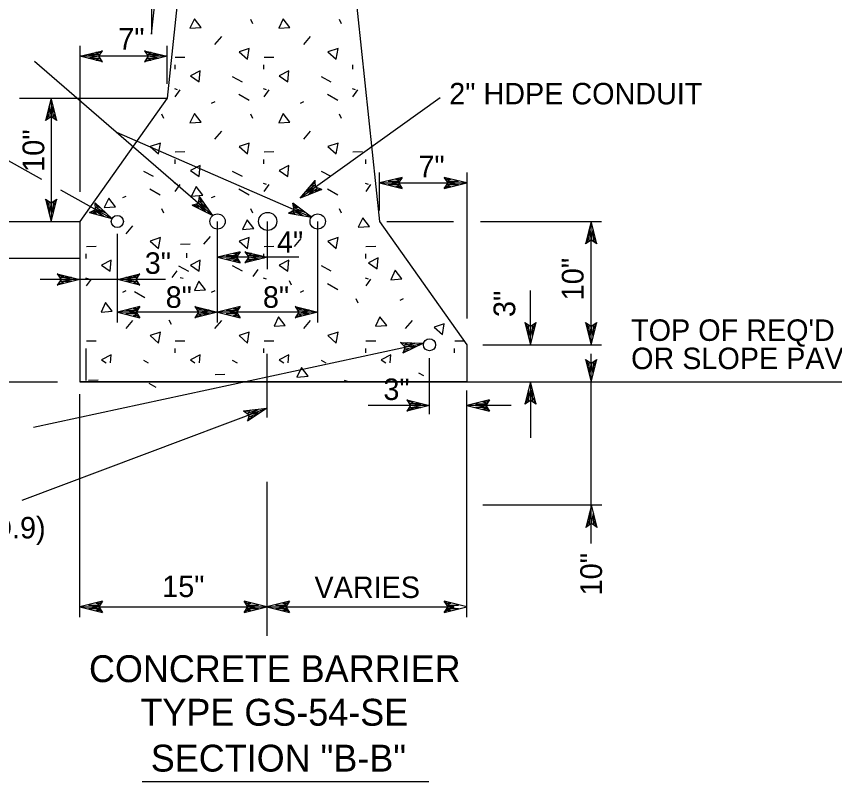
# Model space of a CAD drawing. Extents: x 504255 to 505955, y 659986 to 661086.
# Drawn here: x 504800.9 to 505019.2, y 660598.4 to 660802.7 of the extents above; entities that cross this region are included whole.
import ezdxf

# ---------------------------------------------------------------- set-up
doc = ezdxf.new("R2010")
doc.units = 0
for name, color, linetype in [('Level1', 7, 'Continuous'), ('Level3', 7, 'Continuous'), ('Level63', 7, 'Continuous')]:
    doc.layers.add(name, color=color, linetype=linetype)

msp = doc.modelspace()

# ---------------------------------------------------------------- linework, layer by layer
at = {"layer": 'Level1'}
for p, q in [((504836.94, 660797.95), (504841, 660836.25)), ((504836.94, 660836.25), (504836.94, 660797.95)), ((504817.81, 660794.84), (504817.81, 660755.89)), ((504841.09, 660784.74), (504841.09, 660794.84)), ((504841.09, 660792.07), (504817.81, 660792.07)), ((504805.69, 660790.75), (504853.25, 660749.56)), ((504801.72, 660780.9), (504841.09, 660780.9)), ((504810.12, 660780.9), (504810.12, 660747.99)), ((504913.88, 660780.98), (504876.56, 660754.22)), ((504827.59, 660771.79), (504879.56, 660749.11)), ((504792.67, 660767.62), (504807.54, 660759.29)), ((504897.78, 660750.93), (504897.78, 660761.02)), ((504921.05, 660761.02), (504921.05, 660722.07)), ((504812.63, 660756.44), (504826.35, 660748.74)), ((504897.78, 660758.26), (504921.05, 660758.26)), ((504795.68, 660747.99), (504817.81, 660747.99)), ((504854.52, 660721.03), (504854.52, 660747.99)), ((504867.88, 660735.21), (504867.88, 660747.99)), ((504881.25, 660721.03), (504881.25, 660747.99)), ((504899.7, 660747.99), (504917.49, 660747.99)), ((504924.66, 660747.99), (504957, 660747.99)), ((504954.2, 660715.08), (504954.2, 660747.99)), ((504827.79, 660721.03), (504827.79, 660744.66)), ((504876.24, 660738.42), (504854.52, 660738.42)), ((504840.61, 660732.51), (504807.19, 660732.51)), ((504938.01, 660715.08), (504938.01, 660729.53)), ((504854.52, 660723.79), (504827.79, 660723.79)), ((504881.25, 660723.79), (504854.52, 660723.79)), ((504805.43, 660693.05), (504909.51, 660715.51)), ((504925.29, 660715.08), (504957, 660715.08)), ((504867.68, 660712.65), (504867.68, 660695.64)), ((504911.08, 660696.5), (504911.08, 660711.53)), ((504954.2, 660662), (504954.2, 660712.65)), ((504768.57, 660705.2), (504811.82, 660705.2)), ((504938.01, 660705.2), (504938.01, 660690.18)), ((504817.81, 660642.32), (504817.81, 660701.86)), ((504921.05, 660642.32), (504921.05, 660702.87)), ((504802.41, 660673.61), (504867.67, 660698.15)), ((504911.08, 660698.82), (504894.72, 660698.82)), ((504932.88, 660698.82), (504921.05, 660698.82)), ((504867.69, 660678.46), (504867.69, 660637.37)), ((504925.29, 660672.29), (504957.1, 660672.29)), ((504817.81, 660645.08), (504867.69, 660645.08)), ((504867.69, 660645.08), (504917.56, 660645.08)), ((504834.41, 660598.43), (504910.91, 660598.43))]:
    msp.add_line(p, q, dxfattribs=at)
for points in [[(504847.43, 660840.63), (504841.09, 660780.9)], [(504887.94, 660840.63), (504897.78, 660747.99)], [(504823.85, 660790.58), (504817.81, 660792.07), (504823.85, 660793.57), (504823.14, 660793.07), (504822.09, 660793.07), (504823.1, 660792.57), (504820.08, 660792.57), (504822.77, 660792.07), (504820.08, 660791.57), (504823.1, 660791.57), (504822.09, 660791.08), (504823.14, 660791.08), (504823.85, 660790.58), (504822.85, 660792.07), (504823.85, 660793.57)], [(504835.04, 660793.57), (504841.09, 660792.07), (504835.04, 660790.58), (504835.76, 660791.08), (504836.8, 660791.08), (504835.79, 660791.57), (504838.81, 660791.57), (504836.13, 660792.07), (504838.81, 660792.57), (504835.79, 660792.57), (504836.8, 660793.07), (504835.76, 660793.07), (504835.04, 660793.57), (504836.05, 660792.07), (504835.04, 660790.58)], [(504811.63, 660774.92), (504810.12, 660780.9), (504808.61, 660774.92), (504809.12, 660775.63), (504809.12, 660776.67), (504809.62, 660775.67), (504809.62, 660778.66), (504810.12, 660776), (504810.62, 660778.66), (504810.62, 660775.67), (504811.13, 660776.67), (504811.13, 660775.63), (504811.63, 660774.92), (504810.12, 660775.92), (504808.61, 660774.92)], [(504841.09, 660780.9), (504817.81, 660747.99)], [(504882.32, 660756.51), (504876.56, 660754.22), (504880.56, 660758.93), (504880.27, 660758.11), (504879.43, 660757.51), (504880.55, 660757.69), (504878.1, 660755.93), (504880.57, 660757.1), (504878.68, 660755.13), (504881.14, 660756.89), (504880.61, 660755.89), (504881.45, 660756.51), (504882.32, 660756.51), (504880.63, 660757.14), (504880.56, 660758.93)], [(504903.82, 660759.75), (504897.78, 660758.26), (504903.82, 660756.77), (504903.11, 660757.26), (504902.06, 660757.26), (504903.07, 660757.76), (504900.05, 660757.76), (504902.74, 660758.26), (504900.05, 660758.75), (504903.07, 660758.75), (504902.06, 660759.26), (504903.11, 660759.26), (504903.82, 660759.75), (504902.81, 660758.26), (504903.82, 660756.77)], [(504915.02, 660756.77), (504921.05, 660758.26), (504915.02, 660759.75), (504915.73, 660759.26), (504916.77, 660759.26), (504915.76, 660758.75), (504918.78, 660758.75), (504916.1, 660758.26), (504918.78, 660757.76), (504915.76, 660757.76), (504916.77, 660757.26), (504915.73, 660757.26), (504915.02, 660756.77), (504916.02, 660758.26), (504915.02, 660759.75)], [(504847.72, 660752.37), (504853.25, 660749.56), (504849.7, 660754.62), (504849.91, 660753.78), (504850.69, 660753.1), (504849.6, 660753.38), (504851.88, 660751.41), (504849.52, 660752.79), (504851.22, 660750.66), (504848.94, 660752.64), (504849.37, 660751.6), (504848.59, 660752.28), (504847.72, 660752.37), (504849.47, 660752.84), (504849.7, 660754.62)], [(504808.61, 660753.97), (504810.12, 660747.99), (504811.63, 660753.97), (504811.13, 660753.26), (504811.13, 660752.23), (504810.63, 660753.23), (504810.63, 660750.24), (504810.12, 660752.9), (504809.62, 660750.24), (504809.62, 660753.23), (504809.12, 660752.23), (504809.12, 660753.26), (504808.61, 660753.97), (504810.12, 660752.97), (504811.63, 660753.97)], [(504820.36, 660750.39), (504826.35, 660748.74), (504821.84, 660752.99), (504822.22, 660752.21), (504823.12, 660751.7), (504822, 660751.76), (504824.62, 660750.28), (504822.04, 660751.16), (504824.14, 660749.42), (504821.5, 660750.89), (504822.13, 660749.96), (504821.23, 660750.48), (504820.36, 660750.39), (504821.98, 660751.2), (504821.84, 660752.99)], [(504873.44, 660750.16), (504879.56, 660749.11), (504874.65, 660752.89), (504875.1, 660752.15), (504876.05, 660751.73), (504874.92, 660751.68), (504877.69, 660750.47), (504875.03, 660751.09), (504877.29, 660749.56), (504874.52, 660750.77), (504875.24, 660749.91), (504874.29, 660750.33), (504873.44, 660750.16), (504874.96, 660751.13), (504874.65, 660752.89)], [(504817.81, 660747.99), (504817.81, 660705.2)], [(504897.78, 660747.99), (504921.05, 660715.08)], [(504955.71, 660742.01), (504954.2, 660747.99), (504952.7, 660742.01), (504953.2, 660742.72), (504953.2, 660743.75), (504953.7, 660742.75), (504953.7, 660745.75), (504954.2, 660743.08), (504954.71, 660745.75), (504954.71, 660742.75), (504955.21, 660743.75), (504955.21, 660742.72), (504955.71, 660742.01), (504954.2, 660743.01), (504952.7, 660742.01)], [(504860.56, 660739.92), (504854.52, 660738.42), (504860.56, 660736.93), (504859.85, 660737.43), (504858.8, 660737.43), (504859.81, 660737.93), (504856.79, 660737.93), (504859.47, 660738.42), (504856.79, 660738.92), (504859.81, 660738.92), (504858.8, 660739.42), (504859.85, 660739.42), (504860.56, 660739.92), (504859.55, 660738.42), (504860.56, 660736.93)], [(504861.84, 660739.92), (504867.88, 660738.42), (504861.84, 660736.93), (504862.56, 660737.43), (504863.6, 660737.43), (504862.59, 660737.93), (504865.61, 660737.93), (504862.93, 660738.42), (504865.61, 660738.92), (504862.59, 660738.92), (504863.6, 660739.42), (504862.56, 660739.42), (504861.84, 660739.92), (504862.85, 660738.42), (504861.84, 660736.93)], [(504811.77, 660734), (504817.81, 660732.51), (504811.77, 660731.02), (504812.49, 660731.51), (504813.53, 660731.51), (504812.52, 660732.01), (504815.54, 660732.01), (504812.86, 660732.51), (504815.54, 660733.01), (504812.52, 660733.01), (504813.53, 660733.51), (504812.49, 660733.51), (504811.77, 660734), (504812.78, 660732.51), (504811.77, 660731.02)], [(504833.82, 660731.02), (504827.79, 660732.51), (504833.82, 660734), (504833.11, 660733.51), (504832.07, 660733.51), (504833.08, 660733.01), (504830.06, 660733.01), (504832.74, 660732.51), (504830.06, 660732.01), (504833.08, 660732.01), (504832.07, 660731.51), (504833.11, 660731.51), (504833.82, 660731.02), (504832.82, 660732.51), (504833.82, 660734)], [(504833.83, 660725.29), (504827.79, 660723.79), (504833.83, 660722.3), (504833.11, 660722.8), (504832.07, 660722.8), (504833.08, 660723.3), (504830.06, 660723.3), (504832.74, 660723.79), (504830.06, 660724.29), (504833.08, 660724.29), (504832.07, 660724.79), (504833.11, 660724.79), (504833.83, 660725.29), (504832.82, 660723.79), (504833.83, 660722.3)], [(504848.48, 660725.29), (504854.52, 660723.79), (504848.48, 660722.3), (504849.19, 660722.8), (504850.23, 660722.8), (504849.23, 660723.3), (504852.25, 660723.3), (504849.57, 660723.79), (504852.25, 660724.29), (504849.23, 660724.29), (504850.23, 660724.79), (504849.19, 660724.79), (504848.48, 660725.29), (504849.49, 660723.79), (504848.48, 660722.3)], [(504860.56, 660725.29), (504854.52, 660723.79), (504860.56, 660722.3), (504859.85, 660722.8), (504858.8, 660722.8), (504859.81, 660723.3), (504856.79, 660723.3), (504859.47, 660723.79), (504856.79, 660724.29), (504859.81, 660724.29), (504858.8, 660724.79), (504859.85, 660724.79), (504860.56, 660725.29), (504859.55, 660723.79), (504860.56, 660722.3)], [(504875.21, 660725.29), (504881.25, 660723.79), (504875.21, 660722.3), (504875.92, 660722.8), (504876.97, 660722.8), (504875.96, 660723.3), (504878.98, 660723.3), (504876.3, 660723.79), (504878.98, 660724.29), (504875.96, 660724.29), (504876.97, 660724.79), (504875.92, 660724.79), (504875.21, 660725.29), (504876.22, 660723.79), (504875.21, 660722.3)], [(504936.5, 660721.05), (504938.01, 660715.08), (504939.52, 660721.05), (504939.02, 660720.35), (504939.02, 660719.32), (504938.52, 660720.31), (504938.52, 660717.33), (504938.01, 660719.98), (504937.51, 660717.33), (504937.51, 660720.31), (504937.01, 660719.32), (504937.01, 660720.35), (504936.5, 660721.05), (504938.01, 660720.06), (504939.52, 660721.05)], [(504952.7, 660721.04), (504954.2, 660715.08), (504955.71, 660721.04), (504955.21, 660720.34), (504955.21, 660719.31), (504954.71, 660720.31), (504954.71, 660717.32), (504954.2, 660719.98), (504953.7, 660717.32), (504953.7, 660720.31), (504953.2, 660719.31), (504953.2, 660720.34), (504952.7, 660721.04), (504954.2, 660720.05), (504955.71, 660721.04)], [(504903.3, 660715.7), (504909.51, 660715.51), (504903.94, 660712.78), (504904.53, 660713.42), (504905.54, 660713.64), (504904.45, 660713.91), (504907.4, 660714.56), (504904.67, 660714.47), (504907.19, 660715.52), (504904.24, 660714.88), (504905.12, 660715.59), (504904.1, 660715.36), (504903.3, 660715.7), (504904.6, 660714.45), (504903.94, 660712.78)], [(504921.05, 660715.08), (504921.05, 660705.2)], [(504952.7, 660711.17), (504954.2, 660705.2), (504955.71, 660711.17), (504955.21, 660710.47), (504955.21, 660709.44), (504954.71, 660710.44), (504954.71, 660707.45), (504954.2, 660710.11), (504953.7, 660707.45), (504953.7, 660710.44), (504953.2, 660709.44), (504953.2, 660710.47), (504952.7, 660711.17), (504954.2, 660710.18), (504955.71, 660711.17)], [(504921.05, 660705.2), (504817.81, 660705.2)], [(504939.52, 660699.23), (504938.01, 660705.2), (504936.5, 660699.23), (504937.01, 660699.93), (504937.01, 660700.96), (504937.51, 660699.96), (504937.51, 660702.96), (504938.01, 660700.29), (504938.51, 660702.96), (504938.51, 660699.96), (504939.02, 660700.96), (504939.02, 660699.93), (504939.52, 660699.23), (504938.01, 660700.22), (504936.5, 660699.23)], [(504905.04, 660700.32), (504911.08, 660698.82), (504905.04, 660697.33), (504905.75, 660697.83), (504906.79, 660697.83), (504905.79, 660698.33), (504908.8, 660698.33), (504906.12, 660698.82), (504908.8, 660699.32), (504905.79, 660699.32), (504906.79, 660699.82), (504905.75, 660699.82), (504905.04, 660700.32), (504906.05, 660698.82), (504905.04, 660697.33)], [(504927.09, 660700.32), (504921.05, 660698.82), (504927.09, 660697.33), (504926.38, 660697.83), (504925.34, 660697.83), (504926.34, 660698.33), (504923.32, 660698.33), (504926.01, 660698.82), (504923.32, 660699.32), (504926.34, 660699.32), (504925.34, 660699.82), (504926.38, 660699.82), (504927.09, 660700.32), (504926.08, 660698.82), (504927.09, 660697.33)], [(504861.49, 660697.43), (504867.67, 660698.15), (504862.56, 660694.63), (504863.05, 660695.35), (504864.02, 660695.72), (504862.9, 660695.83), (504865.72, 660696.9), (504863.04, 660696.41), (504865.38, 660697.82), (504862.55, 660696.76), (504863.31, 660697.58), (504862.34, 660697.21), (504861.49, 660697.43), (504862.97, 660696.38), (504862.56, 660694.63)], [(504955.82, 660666.31), (504954.31, 660672.29), (504952.8, 660666.31), (504953.31, 660667.01), (504953.31, 660668.05), (504953.81, 660667.05), (504953.81, 660670.04), (504954.31, 660667.38), (504954.81, 660670.04), (504954.81, 660667.05), (504955.31, 660668.05), (504955.31, 660667.01), (504955.82, 660666.31), (504954.31, 660667.31), (504952.8, 660666.31)], [(504823.86, 660646.58), (504817.81, 660645.08), (504823.86, 660643.59), (504823.14, 660644.09), (504822.1, 660644.09), (504823.1, 660644.58), (504820.09, 660644.58), (504822.77, 660645.08), (504820.09, 660645.58), (504823.1, 660645.58), (504822.1, 660646.08), (504823.14, 660646.08), (504823.86, 660646.58), (504822.85, 660645.08), (504823.86, 660643.59)], [(504861.65, 660643.59), (504867.69, 660645.08), (504861.65, 660646.58), (504862.36, 660646.08), (504863.41, 660646.08), (504862.4, 660645.58), (504865.42, 660645.58), (504862.73, 660645.08), (504865.42, 660644.58), (504862.4, 660644.58), (504863.41, 660644.09), (504862.36, 660644.09), (504861.65, 660643.59), (504862.65, 660645.08), (504861.65, 660646.58)], [(504873.73, 660646.58), (504867.69, 660645.08), (504873.73, 660643.59), (504873.01, 660644.09), (504871.97, 660644.09), (504872.98, 660644.58), (504869.96, 660644.58), (504872.64, 660645.08), (504869.96, 660645.58), (504872.98, 660645.58), (504871.97, 660646.08), (504873.01, 660646.08), (504873.73, 660646.58), (504872.72, 660645.08), (504873.73, 660643.59)], [(504915.02, 660643.59), (504921.05, 660645.08), (504915.02, 660646.58), (504915.73, 660646.08), (504916.77, 660646.08), (504915.76, 660645.58), (504918.78, 660645.58), (504916.1, 660645.08), (504918.78, 660644.58), (504915.76, 660644.58), (504916.77, 660644.09), (504915.73, 660644.09), (504915.02, 660643.59), (504916.02, 660645.08), (504915.02, 660646.58)]]:
    msp.add_lwpolyline(points, dxfattribs=at)
for points in [[(504829.34, 660750.54), (504829.34, 660750.54), (504829.35, 660750.54)], [(505010.52, 660705.2), (505010.52, 660705.2), (505010.52, 660705.2)]]:
    msp.add_lwpolyline(points, close=True, dxfattribs=at)
at = {"layer": 'Level3'}
for p, q in [((504863.29, 660801.98), (504863.84, 660800.83)), ((504886.98, 660801.98), (504887.54, 660800.83)), ((504855.55, 660797.34), (504853.71, 660795.2)), ((504879.25, 660797.34), (504877.42, 660795.2)), ((504845.84, 660791.8), (504843.22, 660791.75)), ((504869.54, 660791.8), (504866.93, 660791.75)), ((504843.09, 660789.81), (504843.09, 660788.63)), ((504866.8, 660789.81), (504866.8, 660788.63)), ((504890.49, 660789.81), (504890.49, 660788.63)), ((504858.43, 660786.69), (504861.08, 660785.28)), ((504882.13, 660786.69), (504884.78, 660785.28)), ((504843.88, 660783.13), (504843.09, 660783.36)), ((504844.47, 660783.13), (504843.15, 660781.27)), ((504867.58, 660783.13), (504866.8, 660783.36)), ((504868.17, 660783.13), (504866.85, 660781.27)), ((504891.29, 660783.13), (504890.49, 660783.36)), ((504891.88, 660783.13), (504890.56, 660781.27)), ((504860.18, 660781.97), (504862.92, 660780.36)), ((504883.88, 660781.97), (504886.62, 660780.36)), ((504852.94, 660779.6), (504853.88, 660780.04)), ((504876.64, 660779.6), (504877.58, 660780.04)), ((504839.59, 660776.72), (504840.14, 660775.58)), ((504863.29, 660776.72), (504863.84, 660775.58)), ((504886.98, 660776.72), (504887.54, 660775.58)), ((504855.55, 660772.08), (504853.71, 660769.96)), ((504879.25, 660772.08), (504877.42, 660769.96)), ((504845.84, 660766.55), (504843.22, 660766.49)), ((504869.54, 660766.55), (504866.93, 660766.49)), ((504893.24, 660766.55), (504890.62, 660766.49)), ((504843.09, 660764.56), (504843.09, 660763.38)), ((504866.8, 660764.56), (504866.8, 660763.38)), ((504893.99, 660764.56), (504893.99, 660763.38)), ((504834.73, 660761.45), (504837.38, 660760.04)), ((504858.43, 660761.45), (504861.08, 660760.04)), ((504882.13, 660761.45), (504884.78, 660760.04)), ((504836.48, 660756.72), (504839.23, 660755.11)), ((504843.88, 660757.88), (504843.09, 660758.11)), ((504844.47, 660757.88), (504843.15, 660756.02)), ((504860.18, 660756.72), (504862.92, 660755.11)), ((504867.58, 660757.88), (504866.8, 660758.11)), ((504868.17, 660757.88), (504866.85, 660756.02)), ((504883.88, 660756.72), (504886.62, 660755.11)), ((504894.78, 660757.88), (504893.99, 660758.11)), ((504895.37, 660757.88), (504894.05, 660756.02)), ((504829.24, 660754.35), (504830.17, 660754.78)), ((504852.94, 660754.35), (504853.88, 660754.78)), ((504876.64, 660754.35), (504877.58, 660754.78)), ((504839.59, 660751.47), (504840.14, 660750.32)), ((504863.29, 660751.47), (504863.84, 660750.32)), ((504886.98, 660751.47), (504887.54, 660750.32)), ((504831.85, 660746.83), (504830.02, 660744.7)), ((504852.59, 660744.01), (504850.75, 660741.88)), ((504876.76, 660743.42), (504874.93, 660741.29)), ((504822.14, 660741.3), (504819.52, 660741.24)), ((504847.26, 660741.88), (504844.64, 660741.82)), ((504869.54, 660741.3), (504866.93, 660741.24)), ((504896.74, 660741.3), (504894.12, 660741.24)), ((504819.39, 660739.31), (504819.39, 660738.13)), ((504846.26, 660739.48), (504846.26, 660738.29)), ((504866.8, 660739.31), (504866.8, 660738.13)), ((504893.99, 660739.31), (504893.99, 660738.13)), ((504843.69, 660734.84), (504842.37, 660732.98)), ((504844.15, 660736.11), (504846.8, 660734.7)), ((504858.43, 660736.19), (504861.08, 660734.78)), ((504865.29, 660735.18), (504863.96, 660733.33)), ((504882.13, 660736.19), (504884.78, 660734.78)), ((504820.18, 660732.62), (504819.39, 660732.86)), ((504820.78, 660732.62), (504819.45, 660730.76)), ((504845.34, 660732.73), (504844.54, 660732.97)), ((504867.58, 660732.62), (504866.8, 660732.86)), ((504894.78, 660732.62), (504893.99, 660732.86)), ((504895.37, 660732.62), (504894.05, 660730.76)), ((504873.63, 660732.24), (504874.19, 660731.09)), ((504883.88, 660731.46), (504886.62, 660729.85)), ((504829.24, 660729.09), (504830.17, 660729.53)), ((504832.39, 660729.25), (504835.13, 660727.64)), ((504852.94, 660729.09), (504853.88, 660729.53)), ((504876.64, 660729.09), (504877.58, 660729.53)), ((504891.39, 660727.42), (504891.95, 660726.28)), ((504903.23, 660726.98), (504904.17, 660727.42)), ((504831.85, 660721.57), (504830.02, 660719.45)), ((504841.57, 660721.69), (504842.12, 660720.54)), ((504855.55, 660721.57), (504853.71, 660719.45)), ((504879.25, 660721.57), (504877.42, 660719.45)), ((504906.44, 660721.57), (504904.61, 660719.45)), ((504822.14, 660716.05), (504819.52, 660715.99)), ((504845.84, 660716.05), (504843.22, 660715.99)), ((504869.54, 660716.05), (504866.93, 660715.99)), ((504896.74, 660716.05), (504894.12, 660715.99)), ((504920.44, 660716.05), (504917.83, 660715.99)), ((504819.39, 660714.06), (504819.39, 660705.54)), ((504843.09, 660714.06), (504843.09, 660712.87)), ((504866.8, 660714.06), (504866.8, 660712.87)), ((504893.99, 660714.06), (504893.99, 660712.87)), ((504917.69, 660714.06), (504917.69, 660712.87)), ((504834.73, 660710.93), (504836.04, 660710.24)), ((504858.43, 660710.93), (504859.75, 660710.24)), ((504882.13, 660710.93), (504883.45, 660710.24)), ((504856.46, 660707.09), (504853.85, 660707.04)), ((504908.18, 660707.53), (504909.5, 660706.83)), ((504822.69, 660705.62), (504820.08, 660705.55)), ((504836.18, 660704.78), (504838.09, 660703.76)), ((504889.21, 660705.29), (504888.42, 660705.53))]:
    msp.add_line(p, q, dxfattribs=at)
for points in [[(504848.35, 660802.09), (504847.16, 660799.55), (504850.13, 660799.76)], [(504872.04, 660802.09), (504870.85, 660799.55), (504873.83, 660799.76)], [(504862.97, 660794.17), (504860.29, 660793.27), (504862.5, 660791.29)], [(504886.67, 660794.17), (504883.99, 660793.27), (504886.2, 660791.29)], [(504847.27, 660786.83), (504849.59, 660785.25), (504849.88, 660788.18)], [(504870.97, 660786.83), (504873.3, 660785.25), (504873.58, 660788.18)], [(504848.35, 660776.83), (504847.16, 660774.29), (504850.13, 660774.51)], [(504872.04, 660776.83), (504870.85, 660774.29), (504873.83, 660774.51)], [(504839.27, 660768.91), (504836.59, 660768.01), (504838.8, 660766.03)], [(504862.97, 660768.91), (504860.29, 660768.01), (504862.5, 660766.03)], [(504886.67, 660768.91), (504883.99, 660768.01), (504886.2, 660766.03)], [(504847.27, 660761.59), (504849.59, 660759.99), (504849.88, 660762.92)], [(504870.97, 660761.59), (504873.3, 660759.99), (504873.58, 660762.92)], [(504848.79, 660757.29), (504847.6, 660754.75), (504850.57, 660754.97)], [(504825.5, 660754.23), (504824.31, 660751.69), (504827.29, 660751.91)], [(504862.41, 660748.41), (504861.22, 660745.87), (504864.2, 660746.09)], [(504893.29, 660748.96), (504892.09, 660746.42), (504895.07, 660746.64)], [(504839.27, 660743.66), (504836.59, 660742.76), (504838.8, 660740.78)], [(504862.97, 660743.66), (504860.29, 660742.76), (504862.5, 660740.78)], [(504886.67, 660743.66), (504883.99, 660742.76), (504886.2, 660740.78)], [(504823.57, 660736.32), (504825.89, 660734.74), (504826.18, 660737.67)], [(504847.27, 660736.32), (504849.59, 660734.74), (504849.88, 660737.67)], [(504870.97, 660736.32), (504873.3, 660734.74), (504873.58, 660737.67)], [(504894.76, 660736.94), (504897.09, 660735.35), (504897.37, 660738.29)], [(504901.93, 660734.97), (504900.74, 660732.43), (504903.72, 660732.65)], [(504849.57, 660732.06), (504848.37, 660729.52), (504851.34, 660729.74)], [(504824.65, 660726.33), (504823.45, 660723.78), (504826.43, 660724)], [(504870.83, 660722.56), (504869.64, 660720.01), (504872.61, 660720.23)], [(504897.87, 660722.55), (504896.68, 660720.01), (504899.65, 660720.23)], [(504915.01, 660720.68), (504912.33, 660719.78), (504914.54, 660717.8)], [(504839.27, 660718.4), (504836.59, 660717.51), (504838.8, 660715.53)], [(504862.97, 660718.4), (504860.29, 660717.51), (504862.5, 660715.53)], [(504886.67, 660718.4), (504883.99, 660717.51), (504886.2, 660715.53)], [(504876.91, 660709), (504875.72, 660706.46), (504878.69, 660706.69)]]:
    msp.add_lwpolyline(points, close=True, dxfattribs=at)
for points in [[(504825.97, 660710.24), (504826.18, 660712.42), (504823.57, 660711.08), (504824.79, 660710.24)], [(504849.67, 660710.24), (504849.88, 660712.42), (504847.27, 660711.08), (504848.5, 660710.24)], [(504873.37, 660710.24), (504873.58, 660712.42), (504870.97, 660711.08), (504872.2, 660710.24)], [(504900.57, 660710.24), (504900.78, 660712.42), (504898.17, 660711.08), (504899.4, 660710.24)]]:
    msp.add_lwpolyline(points, dxfattribs=at)
at = {"layer": 'Level63'}
for p, q in [((504817.81, 660738.11), (504625.17, 660738.11)), ((504849.7, 660710.24), (504849.7, 660710.24)), ((504921.05, 660710.24), (504921.05, 660710.24)), ((504817.81, 660705.2), (505079.25, 660705.2))]:
    msp.add_line(p, q, dxfattribs=at)
for centre, major_axis in [((504854.52, 660747.99), (-2.04, 0)), ((504867.89, 660747.99), (-2.44, 0)), ((504881.25, 660747.99), (-2.04, 0)), ((504827.79, 660747.99), (-1.63, 0)), ((504911.08, 660715.07), (1.63, 0))]:
    msp.add_ellipse(centre, major_axis=major_axis, ratio=0.99, dxfattribs=at)

# ---------------------------------------------------------------- texts
at = {"layer": 'Level1'}
for s, height, p in [('7"', 5.739, (504828.05, 660793.88)), ('2" HDPE CONDUIT', 5.7392, (504916.35, 660779.24)), ('7"', 5.739, (504908.12, 660759.79)), ('4"', 5.739, (504870.39, 660739.61)), ('3"', 5.739, (504835.11, 660734)), ('8"', 5.739, (504840.69, 660724.92)), ('8"', 5.739, (504866.63, 660724.94)), ("TOP OF REQ'D PAVING ", 5.7392, (504964.87, 660716.1)), ('OR SLOPE PAVING', 5.7392, (504964.87, 660708.56)), ('3"', 5.739, (504898.78, 660700.32)), ('(SEE NOTE NO.9)', 5.7392, (504744.69, 660663.36)), ('15"', 5.739, (504839.77, 660647.71)), ('VARIES', 5.739, (504880.39, 660647.46)), ('CONCRETE BARRIER', 7.1744, (504820.22, 660625)), ('TYPE GS-54-SE', 7.173, (504833.96, 660613.37)), ('SECTION "B-B"', 7.1744, (504836.71, 660601.12))]:
    msp.add_text(s, height=height, dxfattribs=at).set_placement(p)
for s, p in [('10"', (504808.3, 660761.19)), ('10"', (504952.18, 660726.9)), ('3"', (504933.96, 660722.45)), ('10"', (504957.1, 660648.11))]:
    msp.add_text(s, height=5.797, rotation=90, dxfattribs=at).set_placement(p)

doc.saveas('drawing.dxf')
